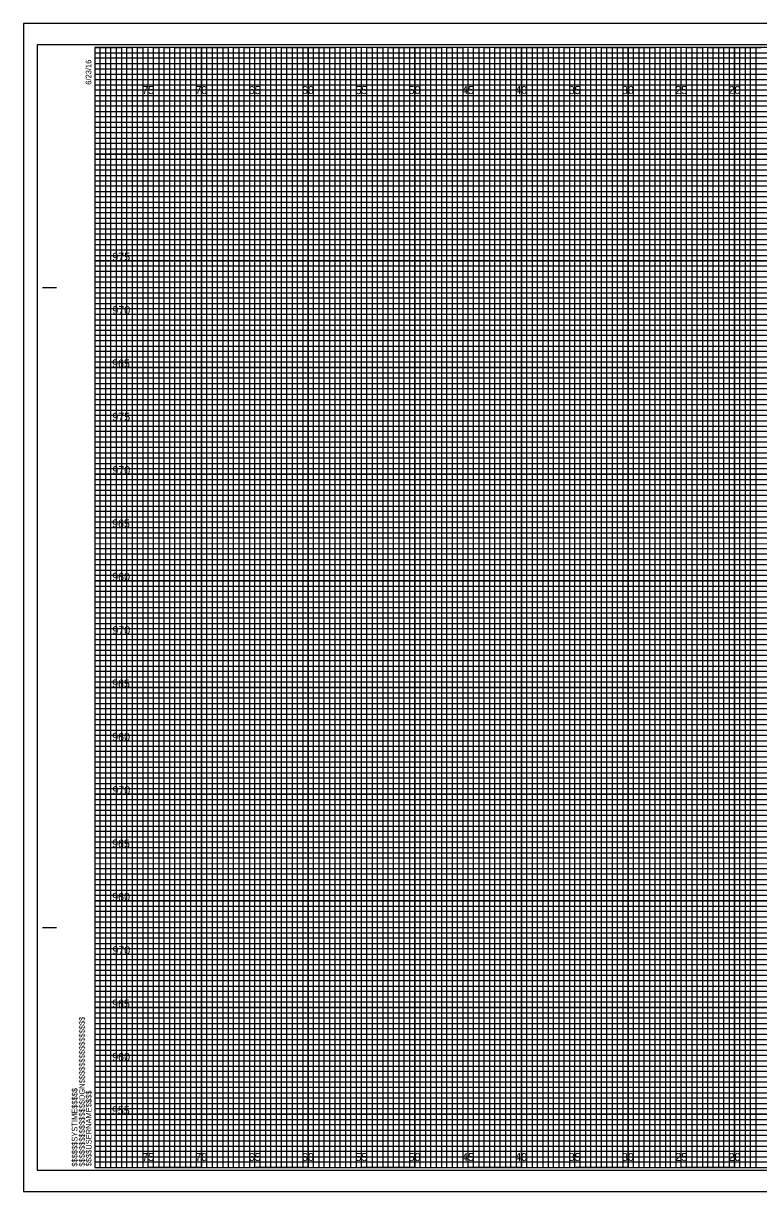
# Model space of a CAD drawing. Extents: x -7 to 162, y -2 to 107.
# Drawn here: x -6.7 to 62.2, y -2.3 to 107.3 of the extents above; entities that cross this region are included whole.
import ezdxf

# ---------------------------------------------------------------- set-up
doc = ezdxf.new("R2010")
doc.units = 0
for name, color, linetype in [('Prop XS Elevation Labels', 7, 'Continuous'), ('Prop XS Offset Labels', 7, 'Continuous'), ('Sheet Cross Section CELL', 7, 'Continuous'), ('Sheet Cross Section Grid Major CELL', 7, 'Continuous'), ('Sheet Cross Section Grid Middle CELL', 7, 'Continuous'), ('Sheet Cross Section Grid Minor 1 CELL', 7, 'Continuous'), ('Sheet Cross Section Grid Minor 2 CELL', 7, 'Continuous'), ('Sheet Cutting Line CELL', 7, 'Continuous'), ('Sheet DOT Grid CELL', 7, 'Continuous'), ('Sheet Plot Border Inside CELL', 7, 'Continuous'), ('Sheet Plot Border Outside CELL', 7, 'Continuous')]:
    doc.layers.add(name, color=color, linetype=linetype)

msp = doc.modelspace()

# ---------------------------------------------------------------- linework, layer by layer
at = {"layer": 'Sheet Cross Section CELL'}
for p, q in [((-4.9, 82.5), (-3.65, 82.5)), ((-4.85, 82.5), (-3.6, 82.5)), ((-4.9, 22.5), (-3.65, 22.5)), ((-4.85, 22.5), (-3.6, 22.5)), ((0, 0), (0, 0)), ((0, 0), (0, 0)), ((0, 0), (0, 0)), ((0, 0), (0, 0)), ((0, 0), (0, 0)), ((0, 0), (0, 0)), ((0, 0), (0, 0))]:
    msp.add_line(p, q, dxfattribs=at)
msp.add_lwpolyline([(160, 105), (0, 105), (0, 0), (160, 0)], close=True, dxfattribs=at)
at = {"layer": 'Sheet Cross Section Grid Major CELL'}
for p, q in [((5, 105), (0, 105)), ((5, 0), (5, 105)), ((15, 105), (10, 105)), ((10, 105), (10, 0)), ((15, 0), (15, 105)), ((25, 105), (20, 105)), ((20, 105), (20, 0)), ((25, 0), (25, 105)), ((35, 105), (30, 105)), ((30, 105), (30, 0)), ((35, 0), (35, 105)), ((45, 105), (40, 105)), ((40, 105), (40, 0)), ((45, 0), (45, 105)), ((55, 105), (50, 105)), ((50, 105), (50, 0)), ((55, 0), (55, 105)), ((65, 105), (60, 105)), ((60, 105), (60, 0)), ((10, 0), (5, 0)), ((20, 0), (15, 0)), ((30, 0), (25, 0)), ((40, 0), (35, 0)), ((50, 0), (45, 0)), ((60, 0), (55, 0))]:
    msp.add_line(p, q, dxfattribs=at)
for points in [[(0, 100), (160, 100), (160, 95), (0, 95)], [(0, 90), (160, 90), (160, 85), (0, 85)], [(0, 80), (160, 80), (160, 75), (0, 75)], [(0, 70), (160, 70), (160, 65), (0, 65)], [(0, 60), (160, 60), (160, 55), (0, 55)], [(0, 50), (160, 50), (160, 45), (0, 45)], [(0, 40), (160, 40), (160, 35), (0, 35)], [(0, 30), (160, 30), (160, 25), (0, 25)], [(0, 20), (160, 20), (160, 15), (0, 15)], [(0, 10), (160, 10), (160, 5), (0, 5)]]:
    msp.add_lwpolyline(points, dxfattribs=at)
at = {"layer": 'Sheet Cross Section Grid Middle CELL'}
for points in [[(0, 105), (2.5, 105), (2.5, 0), (7.5, 0), (7.5, 105), (12.5, 105), (12.5, 0), (17.5, 0), (17.5, 105), (22.5, 105), (22.5, 0), (27.5, 0), (27.5, 105), (32.5, 105), (32.5, 0), (37.5, 0), (37.5, 105), (42.5, 105), (42.5, 0), (47.5, 0), (47.5, 105), (52.5, 105), (52.5, 0), (57.5, 0), (57.5, 105), (62.5, 105)], [(0, 102.5), (137.5, 102.5)], [(0, 92.5), (160, 92.5), (160, 97.5), (0, 97.5)], [(0, 82.5), (160, 82.5), (160, 87.5), (0, 87.5)], [(0, 72.5), (160, 72.5), (160, 77.5), (0, 77.5)], [(0, 62.5), (160, 62.5), (160, 67.5), (0, 67.5)], [(0, 52.5), (160, 52.5), (160, 57.5), (0, 57.5)], [(0, 42.5), (160, 42.5), (160, 47.5), (0, 47.5)], [(0, 32.5), (160, 32.5), (160, 37.5), (0, 37.5)], [(0, 22.5), (160, 22.5), (160, 27.5), (0, 27.5)], [(0, 12.5), (160, 12.5), (160, 17.5), (0, 17.5)], [(0, 2.5), (160, 2.5), (160, 7.5), (0, 7.5)]]:
    msp.add_lwpolyline(points, dxfattribs=at)
at = {"layer": 'Sheet Cross Section Grid Minor 1 CELL'}
for p, q in [((0, 104.5), (130, 104.5)), ((130, 103.99), (0, 103.99)), ((0, 103.99), (0, 103.5)), ((0, 103.5), (130, 103.5)), ((130, 102.95), (0, 102.95)), ((0, 102.95), (0, 102)), ((0, 102), (160, 102))]:
    msp.add_line(p, q, dxfattribs=at)
for points in [[(0, 101.5), (135, 101.5), (160, 101.5), (160, 101), (0, 101)], [(0, 100.5), (160, 100.5), (160, 99.5), (0, 99.5)], [(0, 99), (160, 99), (160, 98.5), (0, 98.49)], [(0, 98), (160, 98), (160, 97), (0, 97)], [(0, 96.5), (160, 96.5), (160, 96), (0, 96)], [(0, 95.5), (160, 95.5), (160, 94.5), (0, 94.5)], [(0, 94), (160, 94), (160, 93.5), (0, 93.5)], [(0, 93), (160, 93), (160, 92), (0, 92)], [(0, 91.5), (160, 91.5), (160, 91), (0, 91)], [(0, 90.5), (160, 90.5), (160, 89.5), (0, 89.5)], [(0, 89), (160, 89), (160, 88.5), (0, 88.5)], [(0, 88), (160, 88), (160, 86.98), (160, 86.5), (160, 86), (0, 86)], [(0, 87), (160, 87), (160, 86.5), (0, 86.5)], [(0, 85.5), (160, 85.5), (160, 84.5), (0, 84.52)], [(0, 84.52), (160, 84.5), (160, 84), (0, 84)], [(0, 83.5), (160, 83.5), (160, 83), (0, 83)], [(0, 82), (160, 82), (160, 81.5), (0, 81.5)], [(0, 81), (160, 81), (160, 80.5), (0, 80.5)], [(-0.04, 79.45), (160, 79.45), (160, 78.94), (-0.04, 78.94)], [(0, 78.5), (160, 78.5), (160, 78), (0, 78)], [(0, 77), (160, 77), (160, 76.5), (0, 76.5)], [(0, 76), (160, 76), (160, 75.5), (0, 75.5)], [(0, 74.5), (160, 74.5), (160, 74), (0, 74)], [(0, 73.5), (160, 73.5), (160, 73), (0, 73)], [(0, 72), (160, 72), (160, 71.5), (0, 71.5)], [(0, 71), (160, 71), (160, 70.5), (0, 70.5)], [(0, 69.5), (160, 69.5), (160, 68.99), (0, 69)], [(0, 68.5), (160, 68.5), (160, 68), (0, 68)], [(0, 67), (160, 67), (160, 66.5), (0, 66.5)], [(0, 66), (160, 66), (160, 65.5), (0, 65.5)], [(0, 64.5), (160, 64.5), (160, 64), (0, 64)], [(0, 63.5), (160, 63.5), (160, 63), (0, 63)], [(0, 62), (160, 62), (160, 61.5), (0, 61.5)], [(0, 61), (160, 61), (160, 60.5), (0, 60.5)], [(0, 59.5), (160, 59.5), (160, 59), (0, 59)], [(0, 58.5), (160.03, 58.45), (160, 58), (0, 58)], [(0, 57), (160, 57), (160, 56.5), (0, 56.5)], [(0, 56), (160, 56), (160, 55.5), (0, 55.5)], [(0, 54.5), (160, 54.5), (160, 54), (0, 54)], [(0, 53.5), (160, 53.5), (160, 53), (0, 53)], [(0, 52), (160, 52), (160, 51.5), (0, 51.5)], [(0, 51), (160, 51), (160, 50.5), (0, 50.5)], [(0, 49.5), (160, 49.5), (160, 49), (0, 49)], [(0, 48.5), (160, 48.5), (160, 48), (0, 48)], [(0, 47), (160, 47), (160, 46.5), (0, 46.5)], [(0, 46), (160, 46), (160, 45.5), (0, 45.5)], [(0, 44.5), (160, 44.5), (160, 44), (0, 44)], [(0, 43.5), (160, 43.5), (160, 43), (0, 43)], [(0, 42), (160, 42), (160, 41.5), (0, 41.5)], [(0, 41), (160, 41), (160, 40.5), (0, 40.5)], [(0, 39.5), (160, 39.5), (160, 38.99), (0, 39)], [(0, 38.5), (160, 38.5), (160, 38), (0, 38)], [(0, 37), (160, 37), (160, 36.5), (0, 36.5)], [(0, 36), (160, 36), (160, 35.5), (0, 35.5)], [(0, 34.5), (160, 34.5), (160, 34), (0, 34)], [(0, 33.5), (160, 33.5), (160, 33), (0, 33)], [(0, 32), (160, 32), (160, 31.5), (0, 31.5)], [(0, 31), (160, 31), (160, 30.5), (0, 30.5)], [(0, 29.5), (160, 29.5), (160, 29), (0, 29)], [(0, 28.5), (160.03, 28.46), (160, 28), (0, 28)], [(0, 27), (160, 27), (160, 26.5), (0, 26.5)], [(0, 26), (160, 26), (160, 25.5), (0, 25.5)], [(0, 24.5), (160, 24.5), (160, 24), (0, 24)], [(0, 23.5), (160, 23.5), (160, 23), (0, 23)], [(0, 22), (160, 22), (160, 21.5), (0, 21.5)], [(0, 21), (160, 21), (160, 20.5), (0, 20.5)], [(0, 19.5), (160, 19.5), (160, 19), (0, 19)], [(0, 18.5), (160, 18.5), (160, 18), (0, 18)], [(0, 17), (160, 17), (160, 16.5), (0, 16.5)], [(0, 16), (160, 16), (160, 15.5), (0, 15.5)], [(0, 14.5), (160, 14.5), (160, 14), (0, 14)], [(0, 13.5), (160, 13.5), (160, 13), (0, 13)], [(0, 12), (160, 12), (160, 11.5), (0, 11.5)], [(0, 11), (160, 11), (160, 10.5), (0, 10.5)], [(0, 9.5), (160, 9.5), (160, 9), (0, 9)], [(0, 8.5), (160, 8.5), (160, 8), (0, 8)], [(0, 7), (160, 7), (160, 6.5), (0, 6.5)], [(0, 6), (160, 6), (160, 5.5), (0, 5.5)], [(0, 4.5), (160, 4.5), (160, 4), (0, 4)], [(0, 3.5), (160, 3.5), (160, 3), (0, 3)], [(0, 2), (160, 2), (160, 1.5), (0, 1.5)], [(0, 1), (160, 1), (160, 0.5), (0, 0.5)]]:
    msp.add_lwpolyline(points, dxfattribs=at)
at = {"layer": 'Sheet Cross Section Grid Minor 2 CELL'}
for points in [[(0, 0), (0.5, 0), (0.5, 105), (1, 105), (1, 0)], [(1, 0), (1.5, 0), (1.5, 105), (2, 105), (2, 0)], [(2.5, 0), (3, 0), (3, 105), (3.5, 105), (3.5, 0)], [(3.5, 0), (4, 0), (4, 105), (4.5, 105), (4.5, 0)], [(5, 0), (5.5, 0), (5.5, 105), (6, 105), (6, 0)], [(6, 0), (6.5, 0), (6.5, 105), (7, 105), (7, 0)], [(7.5, 0), (8, 0), (8, 105), (8.5, 105), (8.5, 0)], [(8.5, 0), (9, 0), (9, 105), (9.5, 105), (9.5, 0)], [(10, 0), (10.5, 0), (10.5, 105), (11, 105), (11, 0)], [(11, 0), (11.5, 0), (11.5, 105), (12, 105), (12, 0)], [(12.5, 0), (13, 0), (13, 105), (13.5, 105), (13.5, 0)], [(13.5, 0), (14, 0), (14, 105), (14.5, 105), (14.5, 0)], [(15, 0), (15.5, 0), (15.5, 105), (16, 105), (16, 0)], [(16, 0), (16.5, 0), (16.5, 105), (17, 105), (17, 0)], [(17.5, 0), (18, 0), (18, 105), (18.5, 105), (18.5, 0)], [(18.5, 0), (19, 0), (19, 105), (19.5, 105), (19.5, 0)], [(20, 0), (20.5, 0), (20.5, 105), (21, 105), (21, 0)], [(21, 0), (21.5, 0), (21.5, 105), (22, 105), (22, 0)], [(22.5, 0), (23, 0), (23, 105), (23.5, 105), (23.5, 0)], [(23.5, 0), (24, 0), (24, 105), (24.5, 105), (24.5, 0)], [(25, 0), (25.5, 0), (25.5, 105), (26, 105), (26, 0)], [(26, 0), (26.5, 0), (26.5, 105), (27, 105), (27, 0)], [(27.5, 0), (28, 0), (28, 105), (28.5, 105), (28.5, 0)], [(28.5, 0), (29, 0), (29, 105), (29.5, 105), (29.5, 0)], [(30, 0), (30.5, 0), (30.5, 105), (31, 105), (31, 0)], [(31, 0), (31.5, 0), (31.5, 105), (32, 105), (32, 0)], [(32.5, 0), (33, 0), (33, 105), (33.5, 105), (33.5, 0)], [(33.5, 0), (34, 0), (34, 105), (34.5, 105), (34.5, 0)], [(35, 0), (35.5, 0), (35.5, 105), (36, 105), (36, 0)], [(36, 0), (36.5, 0), (36.5, 105), (37, 105), (37, 0)], [(37.5, 0), (38, 0), (38, 105), (38.5, 105), (38.5, 0)], [(38.5, 0), (39, 0), (39, 105), (39.5, 105), (39.5, 0)], [(40, 0), (40.5, 0), (40.5, 105), (41, 105), (41, 0)], [(41, 0), (41.5, 0), (41.5, 105), (42, 105), (42, 0)], [(42.5, 0), (43, 0), (43, 105), (43.5, 105), (43.5, 0)], [(43.5, 0), (44, 0), (44, 105), (44.5, 105), (44.5, 0)], [(45, 0), (45.5, 0), (45.5, 105), (46, 105), (46, 0)], [(46, 0), (46.5, 0), (46.5, 105), (47, 105), (47, 0)], [(47.5, 0), (48, 0), (48, 105), (48.5, 105), (48.5, 0)], [(48.5, 0), (49, 0), (49, 105), (49.5, 105), (49.5, 0)], [(50, 0), (50.5, 0), (50.5, 105), (51, 105), (51, 0)], [(51, 0), (51.5, 0), (51.5, 105), (52, 105), (52, 0)], [(52.5, 0), (53, 0), (53, 105), (53.5, 105), (53.5, 0)], [(53.5, 0), (54, 0), (54, 105), (54.5, 105), (54.5, 0)], [(55, 0), (55.5, 0), (55.5, 105), (56, 105), (56, 0)], [(56, 0), (56.5, 0), (56.5, 105), (57, 105), (57, 0)], [(57.5, 0), (58, 0), (58, 105), (58.5, 105), (58.5, 0)], [(58.5, 0), (59, 0), (59, 105), (59.5, 105), (59.5, 0)], [(60, 0), (60.5, 0), (60.5, 105), (61, 105), (61, 0)], [(61, 0), (61.5, 0), (61.5, 105), (62, 105), (62, 0)]]:
    msp.add_lwpolyline(points, dxfattribs=at)
at = {"layer": 'Sheet Cutting Line CELL'}
for p, q in [((161.65, 107.25), (-6.7, 107.25)), ((-6.7, 107.25), (-6.7, -2.25)), ((-6.7, -2.25), (161.65, -2.25))]:
    msp.add_line(p, q, dxfattribs=at)
at = {"layer": 'Sheet DOT Grid CELL'}
for p, q in [((5, 0), (5, 105)), ((10, 0), (10, 105)), ((15, 0), (15, 105)), ((20, 0), (20, 105)), ((25, 0), (25, 105)), ((30, 0), (30, 105)), ((35, 0), (35, 105)), ((40, 0), (40, 105)), ((45, 0), (45, 105)), ((50, 0), (50, 105)), ((55, 0), (55, 105)), ((60, 0), (60, 105)), ((0, 100), (160, 100)), ((0, 95), (160, 95)), ((0, 90), (160, 90)), ((0, 85), (160, 85)), ((0, 80), (160, 80)), ((0, 75), (160, 75)), ((0, 70), (160, 70)), ((0, 65), (160, 65)), ((0, 60), (160, 60)), ((0, 55), (160, 55)), ((0, 50), (160, 50)), ((0, 45), (160, 45)), ((0, 40), (160, 40)), ((0, 35), (160, 35)), ((0, 30), (160, 30)), ((0, 25), (160, 25)), ((0, 20), (160, 20)), ((0, 15), (160, 15)), ((0, 10), (160, 10)), ((0, 5), (160, 5))]:
    msp.add_line(p, q, dxfattribs=at)
at = {"layer": 'Sheet Plot Border Inside CELL'}
msp.add_lwpolyline([(-5.4, -0.25), (161.2, -0.25), (161.2, 105.25), (-5.4, 105.25)], close=True, dxfattribs=at)
at = {"layer": 'Sheet Plot Border Outside CELL'}
msp.add_lwpolyline([(-6.7, -2.25), (161.65, -2.25), (161.65, 107.25), (-6.7, 107.25)], close=True, dxfattribs=at)

# ---------------------------------------------------------------- texts
at = {"layer": 'Prop XS Elevation Labels'}
for s, p in [('975', (1.64, 85)), ('970', (1.65, 80)), ('965', (1.62, 75)), ('975', (1.64, 70)), ('970', (1.65, 65)), ('965', (1.62, 60)), ('960', (1.63, 55)), ('970', (1.65, 50)), ('965', (1.62, 45)), ('960', (1.63, 40)), ('970', (1.65, 35)), ('965', (1.62, 30)), ('960', (1.63, 25)), ('970', (1.65, 20)), ('965', (1.62, 15)), ('960', (1.63, 10)), ('955', (1.6, 5))]:
    msp.add_text(s, height=0.75, dxfattribs=at).set_placement(p)
at = {"layer": 'Prop XS Offset Labels'}
for s, p in [('75', (4.44, 100.62)), ('70', (9.43, 100.62)), ('65', (14.44, 100.62)), ('60', (19.43, 100.62)), ('55', (24.44, 100.62)), ('50', (29.43, 100.62)), ('45', (34.44, 100.62)), ('40', (39.43, 100.62)), ('35', (44.44, 100.62)), ('30', (49.43, 100.62)), ('25', (54.44, 100.62)), ('20', (59.43, 100.62)), ('75', (4.44, 0.62)), ('70', (9.43, 0.62)), ('65', (14.44, 0.62)), ('60', (19.43, 0.62)), ('55', (24.44, 0.62)), ('50', (29.43, 0.62)), ('45', (34.44, 0.62)), ('40', (39.43, 0.62)), ('35', (44.44, 0.62)), ('30', (49.43, 0.62)), ('25', (54.44, 0.62)), ('20', (59.43, 0.62))]:
    msp.add_text(s, height=0.75, dxfattribs=at).set_placement(p)
at = {"layer": 'Sheet Cross Section CELL'}
for s, p in [('6/23/16', (-0.33, 101.5)), ('$$$$$$$$$$$$$$$$DGN$$$$$$$$$$$$$$$$', (-0.94, 0.09)), ('$$$$$$SYSTIME$$$$$', (-1.63, 0.09)), ('$$$$USERNAME$$$$', (-0.31, 0.12))]:
    msp.add_text(s, height=0.525, rotation=90, dxfattribs=at).set_placement(p)

doc.saveas('drawing.dxf')
